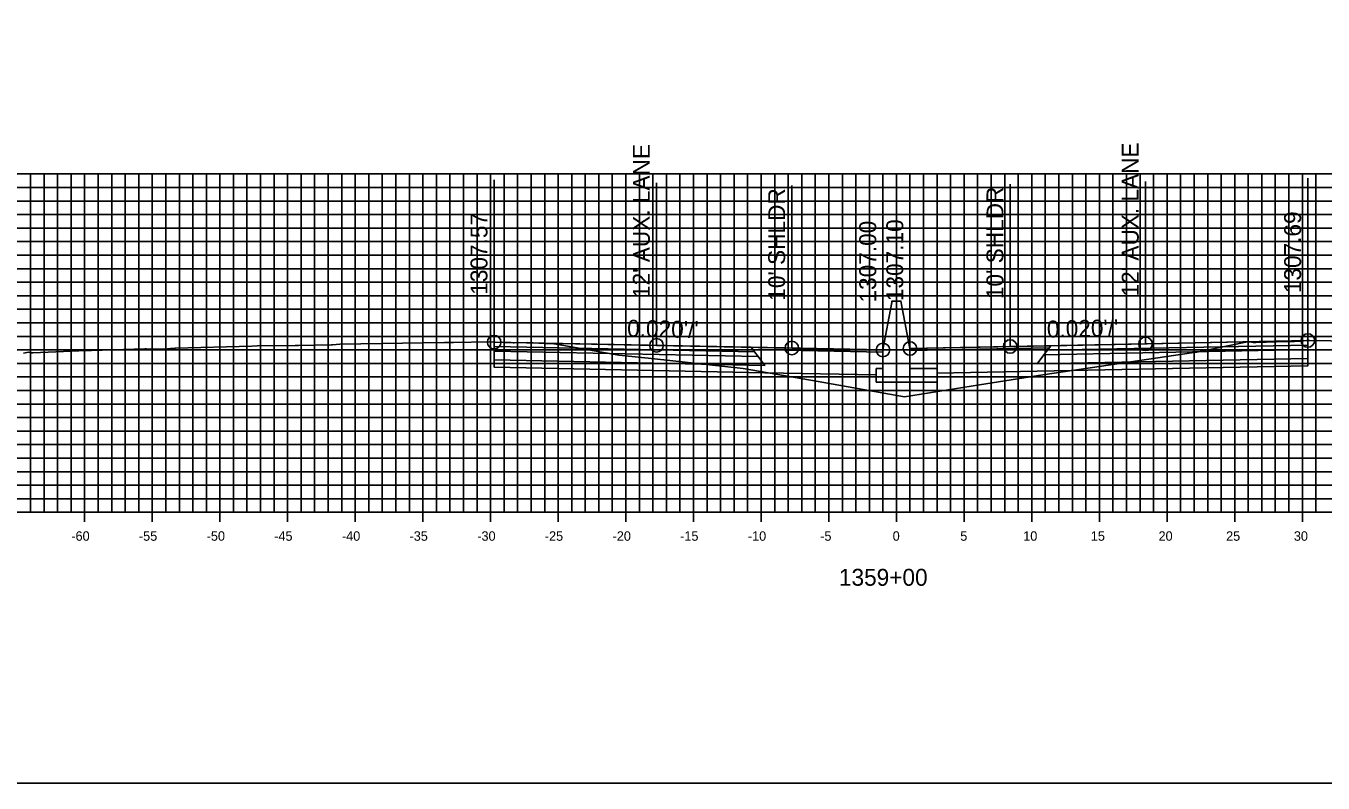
# Model space of a CAD drawing. Extents: x 674939 to 678919, y 750652 to 765176.
# Drawn here: x 678674.2 to 678770.1, y 753912.6 to 753968.5 of the extents above; entities that cross this region are included whole.
import ezdxf

# ---------------------------------------------------------------- set-up
doc = ezdxf.new("R2010")
doc.units = 0
for name, color, linetype in [('R_Alt Surface', 7, 'Continuous'), ('R_Axis', 7, 'Continuous'), ('R_Axis Annot', 7, 'Continuous'), ('R_Exist Surface', 7, 'Continuous'), ('R_Fin Surface', 7, 'Continuous'), ('R_Grid', 7, 'Continuous'), ('R_No Plot', 7, 'Continuous'), ('R_Proposed Road', 7, 'Continuous'), ('R_Xsect Elev', 7, 'Continuous'), ('R_Xsect Slope', 7, 'Continuous')]:
    doc.layers.add(name, color=color, linetype=linetype)

msp = doc.modelspace()

# ---------------------------------------------------------------- linework, layer by layer
at = {"layer": 'R_Alt Surface'}
for points in [[(678708.803, 753944.796), (678708.803, 753944.466), (678728.303, 753944.076), (678728.053, 753944.411)], [(678768.936, 753944.913), (678768.936, 753944.583), (678749.436, 753944.193), (678749.686, 753944.528)], [(678708.803, 753944.466), (678708.803, 753943.806), (678728.803, 753943.406), (678728.303, 753944.076)], [(678768.936, 753944.583), (678768.936, 753943.923), (678748.936, 753943.523), (678749.436, 753944.193)]]:
    msp.add_lwpolyline(points, close=True, dxfattribs=at)
for points in [[(678708.803, 753943.806), (678708.803, 753943.266), (678728.803, 753942.866), (678737.033, 753942.701)], [(678768.936, 753943.923), (678768.936, 753943.383), (678748.936, 753942.983), (678741.533, 753942.835)]]:
    msp.add_lwpolyline(points, dxfattribs=at)
at = {"layer": 'R_Axis'}
for p, q in [((678678.533, 753931.851), (678678.533, 753933.251)), ((678683.533, 753931.851), (678683.533, 753933.251)), ((678688.533, 753931.851), (678688.533, 753933.251)), ((678693.533, 753931.851), (678693.533, 753933.251)), ((678698.533, 753931.851), (678698.533, 753933.251)), ((678703.533, 753931.851), (678703.533, 753933.251)), ((678708.533, 753931.851), (678708.533, 753933.251)), ((678713.533, 753931.851), (678713.533, 753933.251)), ((678718.533, 753931.851), (678718.533, 753933.251)), ((678723.533, 753931.851), (678723.533, 753933.251)), ((678728.533, 753931.851), (678728.533, 753933.251)), ((678733.533, 753931.851), (678733.533, 753933.251)), ((678738.533, 753931.851), (678738.533, 753933.251)), ((678743.533, 753931.851), (678743.533, 753933.251)), ((678748.533, 753931.851), (678748.533, 753933.251)), ((678753.533, 753931.851), (678753.533, 753933.251)), ((678758.533, 753931.851), (678758.533, 753933.251)), ((678763.533, 753931.851), (678763.533, 753933.251)), ((678768.533, 753931.851), (678768.533, 753933.251)), ((678638.533, 753932.551), (678838.533, 753932.551))]:
    msp.add_line(p, q, dxfattribs=at)
at = {"layer": 'R_Exist Surface'}
msp.add_lwpolyline([(678674.017, 753944.302), (678674.393, 753944.374), (678674.581, 753944.334), (678674.711, 753944.34), (678678.664, 753944.499), (678679.042, 753944.51), (678682.994, 753944.627), (678683.112, 753944.626), (678684.429, 753944.61), (678684.89, 753944.648), (678684.907, 753944.649), (678685.199, 753944.674), (678685.241, 753944.677), (678690.885, 753944.832), (678691.276, 753944.841), (678694.099, 753944.878), (678694.336, 753944.883), (678696.782, 753944.926), (678696.806, 753944.924), (678696.841, 753944.928), (678697.406, 753944.978), (678705.118, 753945.092), (678705.807, 753945.101), (678708.441, 753945.137), (678708.803, 753945.126), (678708.804, 753945.126), (678708.863, 753945.123), (678710.194, 753945.081), (678710.289, 753945.081), (678711.23, 753945.093), (678712.547, 753945.034), (678712.642, 753945.03), (678713.018, 753945.031), (678713.389, 753944.971), (678718.013, 753944.171), (678720.642, 753943.888), (678727.192, 753943.168), (678732.746, 753942.217), (678739.139, 753941.083), (678744.67, 753941.967), (678749.357, 753942.705), (678760.515, 753944.357), (678760.648, 753944.376), (678760.724, 753944.392), (678764.476, 753945.155), (678764.501, 753945.157), (678764.625, 753945.136), (678764.906, 753945.088), (678765.085, 753945.099), (678766.628, 753945.144), (678766.986, 753945.163), (678767.106, 753945.155), (678767.948, 753945.168), (678768.426, 753945.188), (678768.846, 753945.24), (678768.912, 753945.244), (678768.936, 753945.243), (678769.05, 753945.25), (678773.79, 753945.171)], dxfattribs=at)
at = {"layer": 'R_Fin Surface'}
for points in [[(678737.533, 753944.551), (678730.803, 753944.686), (678720.803, 753944.886), (678708.803, 753945.126)], [(678768.936, 753945.243), (678756.936, 753945.003), (678746.936, 753944.803), (678739.533, 753944.655)]]:
    msp.add_lwpolyline(points, dxfattribs=at)
for points in [[(678708.803, 753945.126), (678708.803, 753944.796), (678728.053, 753944.411), (678727.803, 753944.746)], [(678727.803, 753944.746), (678737.533, 753944.551), (678737.537, 753944.394), (678727.923, 753944.586)], [(678749.817, 753944.704), (678739.533, 753944.498), (678739.533, 753944.655), (678749.936, 753944.863)], [(678768.936, 753945.243), (678768.936, 753944.913), (678749.686, 753944.528), (678749.936, 753944.863)]]:
    msp.add_lwpolyline(points, close=True, dxfattribs=at)
at = {"layer": 'R_Grid'}
for p, q in [((678638.533, 753957.551), (678838.533, 753957.551)), ((678674.533, 753932.551), (678674.533, 753957.551)), ((678675.533, 753932.551), (678675.533, 753957.551)), ((678676.533, 753932.551), (678676.533, 753957.551)), ((678677.533, 753932.551), (678677.533, 753957.551)), ((678678.533, 753932.551), (678678.533, 753957.551)), ((678679.533, 753932.551), (678679.533, 753957.551)), ((678680.533, 753932.551), (678680.533, 753957.551)), ((678681.533, 753932.551), (678681.533, 753957.551)), ((678682.533, 753932.551), (678682.533, 753957.551)), ((678683.533, 753932.551), (678683.533, 753957.551)), ((678684.533, 753932.551), (678684.533, 753957.551)), ((678685.533, 753932.551), (678685.533, 753957.551)), ((678686.533, 753932.551), (678686.533, 753957.551)), ((678687.533, 753932.551), (678687.533, 753957.551)), ((678688.533, 753932.551), (678688.533, 753957.551)), ((678689.533, 753932.551), (678689.533, 753957.551)), ((678690.533, 753932.551), (678690.533, 753957.551)), ((678691.533, 753932.551), (678691.533, 753957.551)), ((678692.533, 753932.551), (678692.533, 753957.551)), ((678693.533, 753932.551), (678693.533, 753957.551)), ((678694.533, 753932.551), (678694.533, 753957.551)), ((678695.533, 753932.551), (678695.533, 753957.551)), ((678696.533, 753932.551), (678696.533, 753957.551)), ((678697.533, 753932.551), (678697.533, 753957.551)), ((678698.533, 753932.551), (678698.533, 753957.551)), ((678699.533, 753932.551), (678699.533, 753957.551)), ((678700.533, 753932.551), (678700.533, 753957.551)), ((678701.533, 753932.551), (678701.533, 753957.551)), ((678702.533, 753932.551), (678702.533, 753957.551)), ((678703.533, 753932.551), (678703.533, 753957.551)), ((678704.533, 753932.551), (678704.533, 753957.551)), ((678705.533, 753932.551), (678705.533, 753957.551)), ((678706.533, 753932.551), (678706.533, 753957.551)), ((678707.533, 753932.551), (678707.533, 753957.551)), ((678708.533, 753932.551), (678708.533, 753957.551)), ((678709.533, 753932.551), (678709.533, 753957.551)), ((678710.533, 753932.551), (678710.533, 753957.551)), ((678711.533, 753932.551), (678711.533, 753957.551)), ((678712.533, 753932.551), (678712.533, 753957.551)), ((678713.533, 753932.551), (678713.533, 753957.551)), ((678714.533, 753932.551), (678714.533, 753957.551)), ((678715.533, 753932.551), (678715.533, 753957.551)), ((678716.533, 753932.551), (678716.533, 753957.551)), ((678717.533, 753932.551), (678717.533, 753957.551)), ((678718.533, 753932.551), (678718.533, 753957.551)), ((678719.533, 753932.551), (678719.533, 753957.551)), ((678720.533, 753932.551), (678720.533, 753957.551)), ((678721.533, 753932.551), (678721.533, 753957.551)), ((678722.533, 753932.551), (678722.533, 753957.551)), ((678723.533, 753932.551), (678723.533, 753957.551)), ((678724.533, 753932.551), (678724.533, 753957.551)), ((678725.533, 753932.551), (678725.533, 753957.551)), ((678726.533, 753932.551), (678726.533, 753957.551)), ((678727.533, 753932.551), (678727.533, 753957.551)), ((678728.533, 753932.551), (678728.533, 753957.551)), ((678729.533, 753932.551), (678729.533, 753957.551)), ((678730.533, 753932.551), (678730.533, 753957.551)), ((678731.533, 753932.551), (678731.533, 753957.551)), ((678732.533, 753932.551), (678732.533, 753957.551)), ((678733.533, 753932.551), (678733.533, 753957.551)), ((678734.533, 753932.551), (678734.533, 753957.551)), ((678735.533, 753932.551), (678735.533, 753957.551)), ((678736.533, 753932.551), (678736.533, 753957.551)), ((678737.533, 753932.551), (678737.533, 753957.551)), ((678738.533, 753932.551), (678738.533, 753957.551)), ((678739.533, 753932.551), (678739.533, 753957.551)), ((678740.533, 753932.551), (678740.533, 753957.551)), ((678741.533, 753932.551), (678741.533, 753957.551)), ((678742.533, 753932.551), (678742.533, 753957.551)), ((678743.533, 753932.551), (678743.533, 753957.551)), ((678744.533, 753932.551), (678744.533, 753957.551)), ((678745.533, 753932.551), (678745.533, 753957.551)), ((678746.533, 753932.551), (678746.533, 753957.551)), ((678747.533, 753932.551), (678747.533, 753957.551)), ((678748.533, 753932.551), (678748.533, 753957.551)), ((678749.533, 753932.551), (678749.533, 753957.551)), ((678750.533, 753932.551), (678750.533, 753957.551)), ((678751.533, 753932.551), (678751.533, 753957.551)), ((678752.533, 753932.551), (678752.533, 753957.551)), ((678753.533, 753932.551), (678753.533, 753957.551)), ((678754.533, 753932.551), (678754.533, 753957.551)), ((678755.533, 753932.551), (678755.533, 753957.551)), ((678756.533, 753932.551), (678756.533, 753957.551)), ((678757.533, 753932.551), (678757.533, 753957.551)), ((678758.533, 753932.551), (678758.533, 753957.551)), ((678759.533, 753932.551), (678759.533, 753957.551)), ((678760.533, 753932.551), (678760.533, 753957.551)), ((678761.533, 753932.551), (678761.533, 753957.551)), ((678762.533, 753932.551), (678762.533, 753957.551)), ((678763.533, 753932.551), (678763.533, 753957.551)), ((678764.533, 753932.551), (678764.533, 753957.551)), ((678765.533, 753932.551), (678765.533, 753957.551)), ((678766.533, 753932.551), (678766.533, 753957.551)), ((678767.533, 753932.551), (678767.533, 753957.551)), ((678768.533, 753932.551), (678768.533, 753957.551)), ((678769.533, 753932.551), (678769.533, 753957.551)), ((678638.533, 753956.551), (678838.533, 753956.551)), ((678638.533, 753955.551), (678838.533, 753955.551)), ((678638.533, 753954.551), (678838.533, 753954.551)), ((678638.533, 753953.551), (678838.533, 753953.551)), ((678638.533, 753952.551), (678838.533, 753952.551)), ((678638.533, 753951.551), (678838.533, 753951.551)), ((678638.533, 753950.551), (678838.533, 753950.551)), ((678638.533, 753949.551), (678838.533, 753949.551)), ((678638.533, 753948.551), (678838.533, 753948.551)), ((678638.533, 753947.551), (678838.533, 753947.551)), ((678638.533, 753946.551), (678838.533, 753946.551)), ((678638.533, 753945.551), (678838.533, 753945.551)), ((678638.533, 753944.551), (678838.533, 753944.551)), ((678638.533, 753943.551), (678838.533, 753943.551)), ((678638.533, 753942.551), (678838.533, 753942.551)), ((678638.533, 753941.551), (678838.533, 753941.551)), ((678638.533, 753940.551), (678838.533, 753940.551)), ((678638.533, 753939.551), (678838.533, 753939.551)), ((678638.533, 753938.551), (678838.533, 753938.551)), ((678638.533, 753937.551), (678838.533, 753937.551)), ((678638.533, 753936.551), (678838.533, 753936.551)), ((678638.533, 753935.551), (678838.533, 753935.551)), ((678638.533, 753934.551), (678838.533, 753934.551)), ((678638.533, 753933.551), (678838.533, 753933.551)), ((678638.533, 753932.551), (678838.533, 753932.551))]:
    msp.add_line(p, q, dxfattribs=at)
at = {"layer": 'R_No Plot'}
msp.add_lwpolyline([(678578.533, 753912.551), (678918.533, 753912.551), (678918.533, 754132.551), (678578.533, 754132.551)], close=True, dxfattribs=at)
for centre in [(678768.936, 753945.243), (678708.803, 753945.126), (678720.803, 753944.886), (678730.803, 753944.686), (678737.533, 753944.551), (678739.533, 753944.655), (678746.936, 753944.803), (678756.936, 753945.003)]:
    msp.add_circle(centre, 0.5, dxfattribs=at)
at = {"layer": 'R_Proposed Road'}
for points in [[(678738.203, 753948.051), (678737.533, 753944.551)], [(678738.863, 753948.155), (678738.863, 753948.155), (678738.203, 753948.155), (678738.203, 753948.051)], [(678738.863, 753948.155), (678739.533, 753944.655)], [(678737.533, 753944.551), (678737.533, 753943.176), (678737.033, 753943.176), (678737.033, 753942.176), (678741.533, 753942.176), (678741.533, 753943.176), (678739.533, 753943.176), (678739.533, 753944.655)]]:
    msp.add_lwpolyline(points, dxfattribs=at)
at = {"layer": 'R_Xsect Elev'}
for p, q in [((678768.936, 753945.243), (678768.936, 753957.243)), ((678708.803, 753945.126), (678708.803, 753957.126)), ((678720.803, 753944.886), (678720.803, 753956.886)), ((678730.803, 753944.686), (678730.803, 753956.686)), ((678737.533, 753944.551), (678737.533, 753956.551)), ((678739.533, 753944.655), (678739.533, 753956.655)), ((678746.936, 753944.803), (678746.936, 753956.803)), ((678756.936, 753945.003), (678756.936, 753957.003))]:
    msp.add_line(p, q, dxfattribs=at)

# ---------------------------------------------------------------- texts
at = {"layer": 'R_Axis Annot'}
for s, height, p in [('-60', 0.7, (678677.552, 753930.451)), ('-55', 0.7, (678682.546, 753930.451)), ('-50', 0.7, (678687.552, 753930.451)), ('-45', 0.7, (678692.546, 753930.451)), ('-40', 0.7, (678697.552, 753930.451)), ('-35', 0.7, (678702.546, 753930.451)), ('-30', 0.7, (678707.552, 753930.451)), ('-25', 0.7, (678712.546, 753930.451)), ('-20', 0.7, (678717.552, 753930.451)), ('-15', 0.7, (678722.546, 753930.451)), ('-10', 0.7, (678727.552, 753930.451)), ('-5', 0.7, (678732.896, 753930.451)), ('0', 0.7, (678738.252, 753930.451)), ('5', 0.7, (678743.246, 753930.451)), ('10', 0.7, (678747.902, 753930.451)), ('15', 0.7, (678752.896, 753930.451)), ('20', 0.7, (678757.902, 753930.451)), ('25', 0.7, (678762.896, 753930.451)), ('30', 0.7, (678767.902, 753930.451)), ('1359+00', 1.25, (678734.281, 753927.126))]:
    msp.add_text(s, height=height, dxfattribs=at).set_placement(p)
at = {"layer": 'R_Xsect Elev'}
for s, p in [("12' AUX. LANE", (678720.303, 753948.386)), ("12' AUX. LANE", (678756.436, 753948.503)), ("10' SHLDR", (678730.303, 753948.186)), ("10' SHLDR", (678746.436, 753948.303)), ('1307.57', (678708.303, 753948.626)), ('1307.69', (678768.436, 753948.743)), ('1307.00', (678737.033, 753948.051)), ('1307.10', (678739.033, 753948.155))]:
    msp.add_text(s, height=1.25, rotation=90, dxfattribs=at).set_placement(p)
at = {"layer": 'R_Xsect Slope'}
for rotation, p in [(358.85424, (678718.618, 753945.53)), (1.14576, (678749.661, 753945.458))]:
    msp.add_text("0.020'/'", height=1.25, rotation=rotation, dxfattribs=at).set_placement(p)

doc.saveas('drawing.dxf')
